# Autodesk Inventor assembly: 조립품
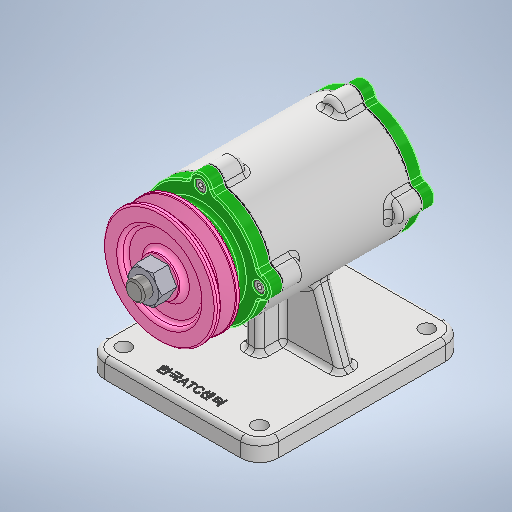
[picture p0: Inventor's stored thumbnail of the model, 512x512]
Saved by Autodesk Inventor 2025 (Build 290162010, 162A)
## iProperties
Created: 2024-08
Part Number: 조립품
Document SubType Name: Assembly
Designer: 학생
Author: 학생
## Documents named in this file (12)
- C:\Users\학생\Desktop\740807V1004\조립품.iam
- C:\Users\학생\Desktop\740807V1004\본체.ipt
- C:\Users\학생\Desktop\740807V1004\740807V1004\Ű 4 x 4\Ű 4 x 4.ipt
- C:\Users\학생\Desktop\740807V1004\740807V1004\V-벨트풀리\V-벨트풀리.ipt
- C:\Users\학생\Desktop\740807V1004\740807V1004\개스킷\개스킷.ipt
- C:\Users\학생\Desktop\740807V1004\740807V1004\너트 M12 x 1.25\너트 M12 x 1.25.ipt
- C:\Users\학생\Desktop\740807V1004\740807V1004\뒤커버\뒤커버.ipt
- C:\Users\학생\Desktop\740807V1004\740807V1004\베어링 6204\베어링 6204.ipt
- C:\Users\학생\Desktop\740807V1004\740807V1004\볼트 M4 x 12\볼트 M4 x 12.ipt
- C:\Users\학생\Desktop\740807V1004\740807V1004\앞커버\앞커버.ipt
- C:\Users\학생\Desktop\740807V1004\740807V1004\오일실\오일실.ipt
- C:\Users\학생\Desktop\740807V1004\740807V1004\축\축.ipt
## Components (4 placed, 3 different names)
1. Ű 4 x 4:1 — 각도:2
2. V-벨트풀리:1 — 각도:2
3. 개스킷:1
4. 개스킷:2
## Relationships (1: Angle 1)
- 각도:2 [Angle]: Ű 4 x 4:1 ↔ V-벨트풀리:1
